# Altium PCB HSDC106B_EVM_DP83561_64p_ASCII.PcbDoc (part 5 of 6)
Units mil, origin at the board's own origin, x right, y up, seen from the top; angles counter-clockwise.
Board outline 8750.24 x 6394.7 mil, 6 copper layers (Top Layer, GND, SIG1, SIG2, GND1, Bottom Layer), stack 60.4 mil thick; 475 components, 330 nets, 1628 pads, 1086 vias.
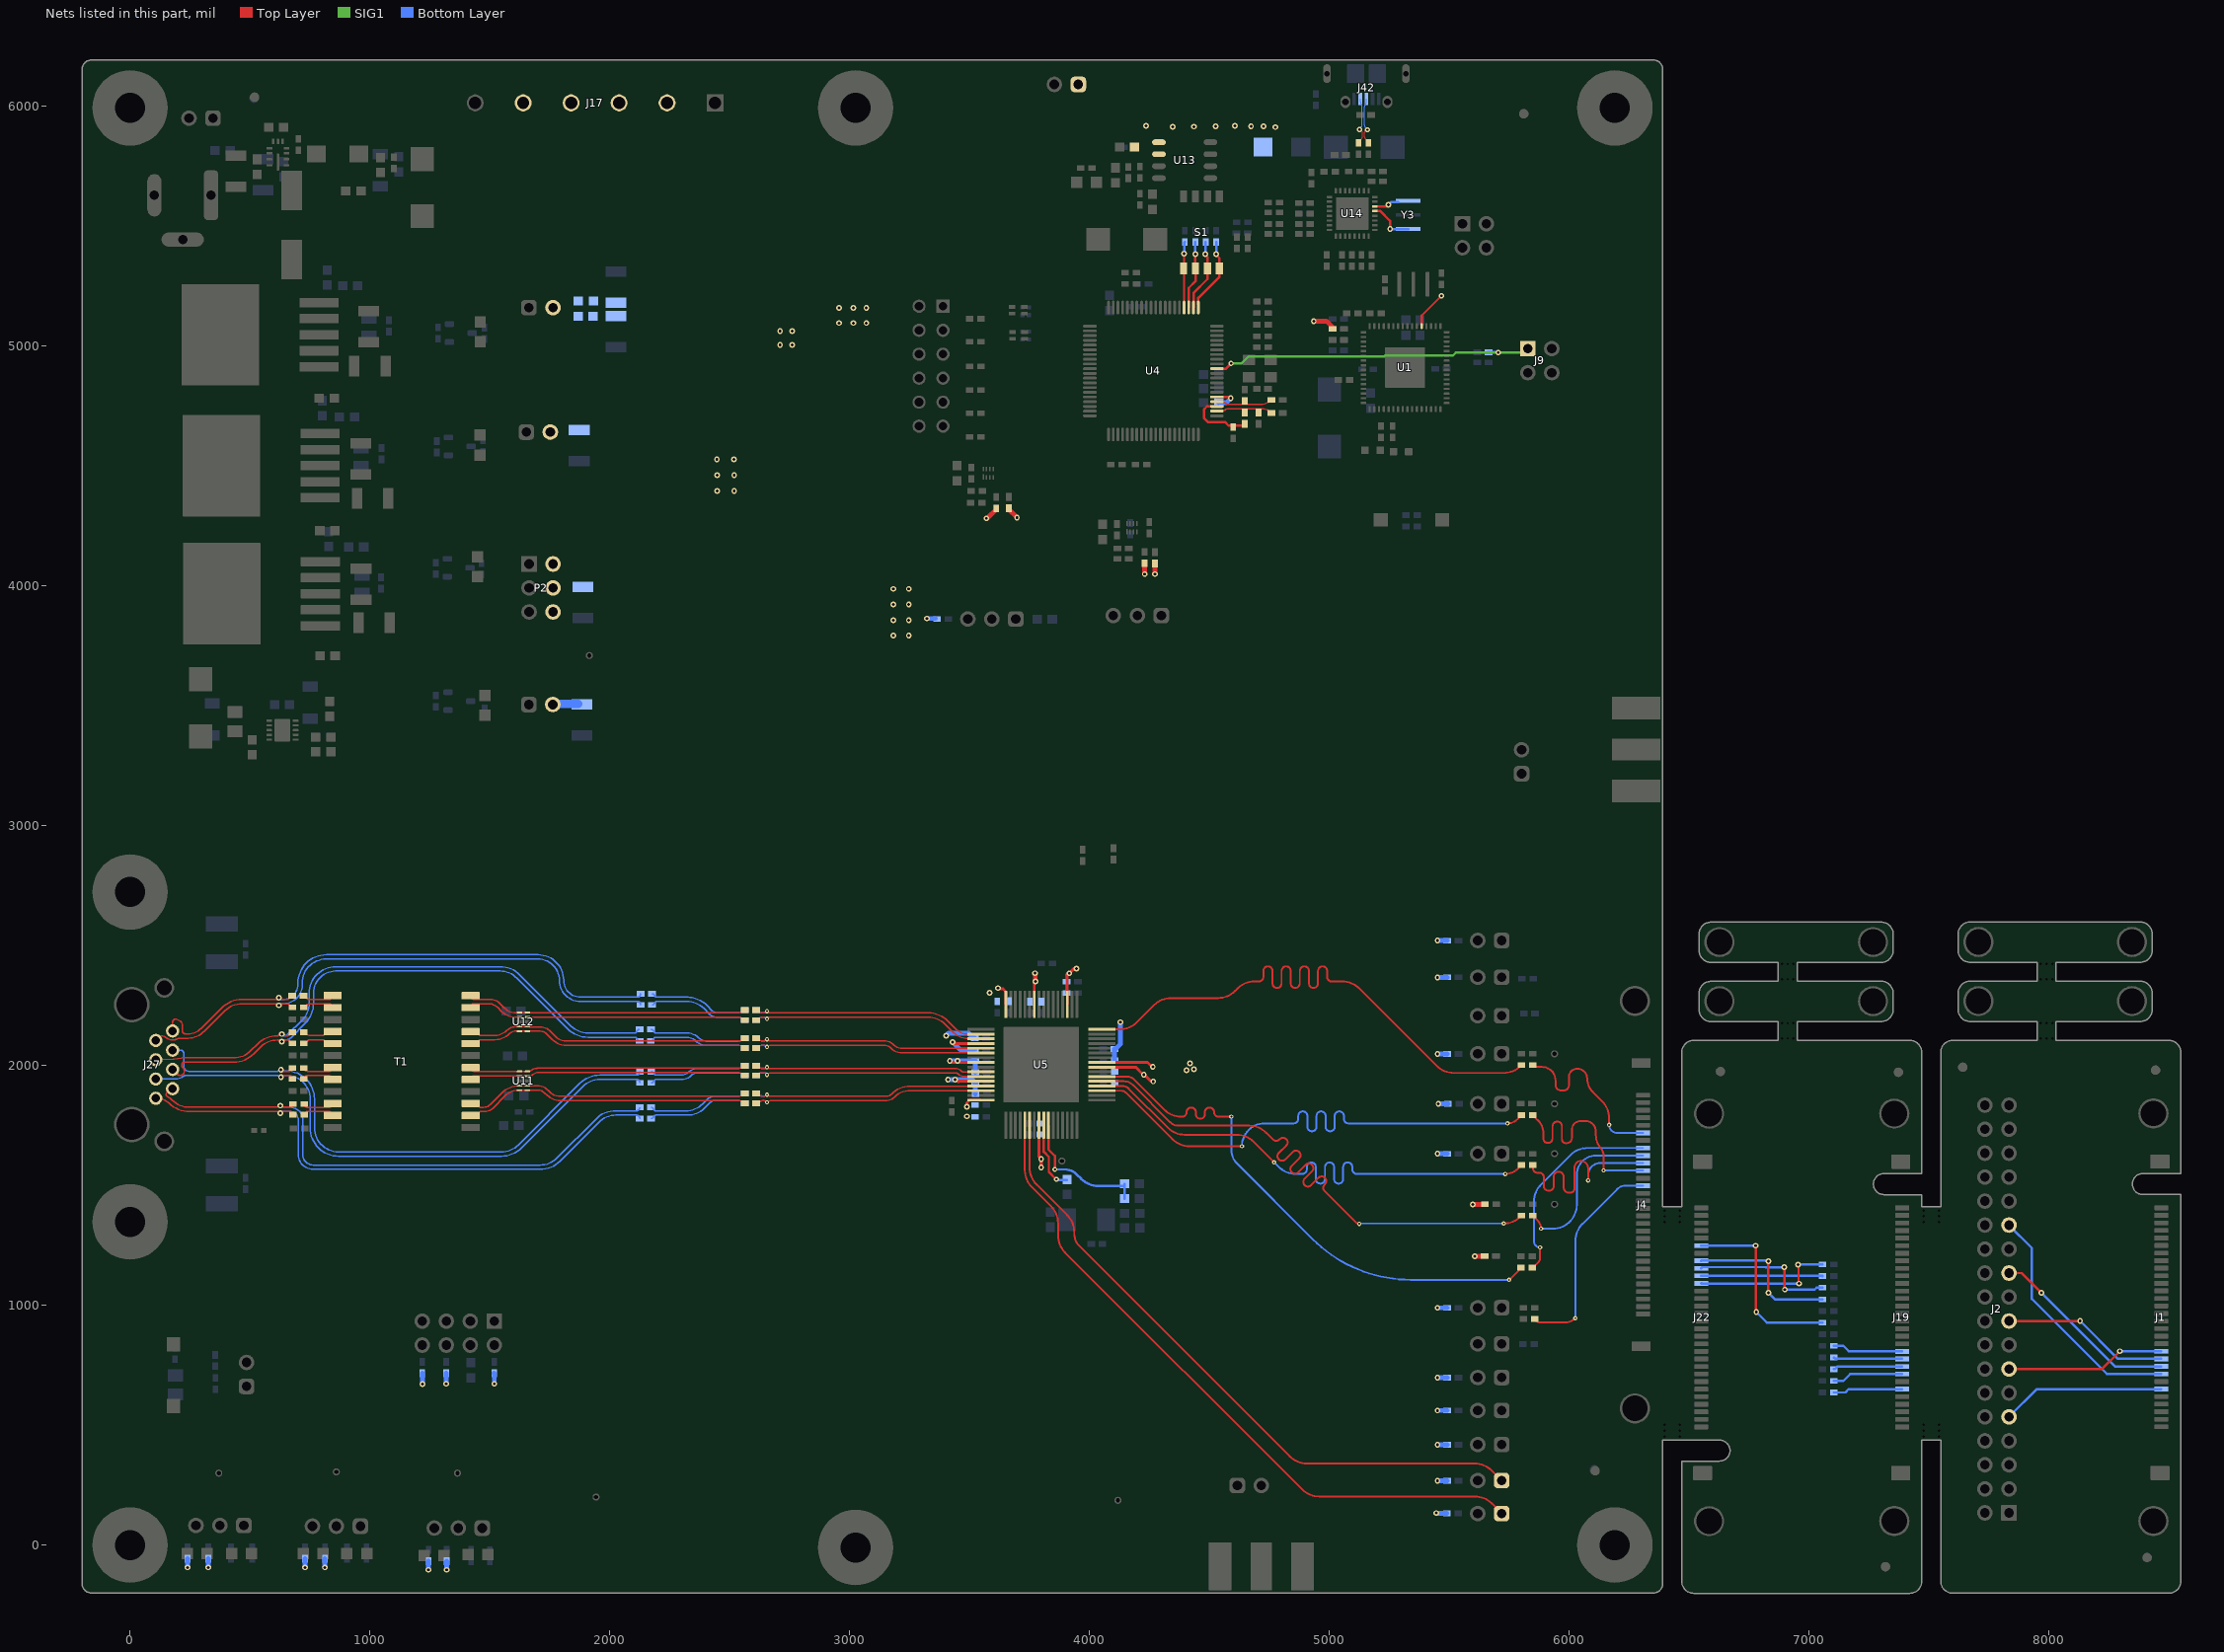
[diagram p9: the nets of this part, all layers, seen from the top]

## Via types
v1: diameter 24, hole 12, Top Layer to Bottom Layer, tented both sides, 905 vias
v2: diameter 24, hole 12, Top Layer to Bottom Layer, 63 vias
v3: diameter 18, hole 7.87, Top Layer to Bottom Layer, tented both sides, 53 vias
v4: diameter 22, hole 10, Top Layer to Bottom Layer, tented both sides, 43 vias
v5: diameter 19.68, hole 7.87, Top Layer to Bottom Layer, 21 vias
v6: diameter 22, hole 12, Top Layer to Bottom Layer, tented both sides, 1 vias

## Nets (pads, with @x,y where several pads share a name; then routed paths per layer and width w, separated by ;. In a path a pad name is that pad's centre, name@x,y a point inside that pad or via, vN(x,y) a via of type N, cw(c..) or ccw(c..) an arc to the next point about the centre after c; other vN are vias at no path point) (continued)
SW1: R65.1 S1.4 U4.1 | length 305.1
  Top Layer w10: U4.1@4453.48,5172.05 4453.48,5201.49 4542,5290.01 S1.4@4542,5324.7 4542,5366.42 4528.6,5379.82 v1(4528.6,5383.61)
  Bottom Layer w10: v1(4528.6,5383.61) R65.1@4528.6,5434.98
SW2: R64.1 S1.3 U4.2 | length 302
  Top Layer w10: U4.2@4433.8,5161.23 4433.8,5221.8 4492,5280.01 S1.3@4492,5324.7 4492,5371.16 4483.34,5379.82 v1(4483.34,5383.61)
  Bottom Layer w10: v1(4483.34,5383.61) 4483.97,5384.24 4483.97,5434.35 R64.1@4484.6,5434.98
SW3: R63.1 S1.2 U4.3 | length 285.5
  Top Layer w10: U4.3@4414.11,5161.23 4414.11,5243.12 4442,5271.01 S1.2@4442,5324.7 4441.6,5325.1 v1(4441.6,5383.61)
  Bottom Layer w10: v1(4441.6,5383.61) R63.1@4441.6,5434.98
SW4: R62.1 S1.1 U4.4 | length 277.1
  Top Layer w10: U4.4@4394.43,5161.23 4394.43,5322.27 S1.1@4392,5324.7 4394.6,5327.3 v1(4394.6,5385.61)
  Bottom Layer w10: v1(4394.6,5385.61) 4396.1,5387.11 4396.1,5433.48 R62.1@4397.6,5434.98
TARGET_D_N: C123.1 R180.1 U4.64 | length 240.4
  Top Layer w6: U4.64@4531.24,4768.51 4547.67,4768.51 cw(c4547.67,4732.03) 4573.46,4757.83 4713.55,4757.83 ccw(c4713.55,4823.21) C123.1@4759.78,4776.98 ; C123.1@4759.78,4775.98 C123.1@4762.5,4778.7
TARGET_D_P: C122.1 R73.2 R183.1 U4.62 | length 240.6
  Top Layer w6: U4.62@4531.24,4729.14 4547.67,4729.14 ccw(c4547.67,4765.62) 4573.46,4739.83 4718.6,4739.83 cw(c4718.6,4692.07) 4752.36,4725.84 C122.1@4761.5,4716.7
TARGET_PUR: R73.1 R74.1 U4.63 | length 287.8
  Top Layer w10: U4.63@4535.36,4749.4 4490.25,4749.4 4477.12,4736.27 4477.12,4700.27 4493.74,4683.65 4564.74,4683.65 4579.74,4668.65 4599.6,4668.65 R73.1@4652.12,4668.65
TD_A_cap_N: C97.1 R124.1 | length 416.9
  Bottom Layer w6: C97.1@2176.22,2252.61 ccw(c2176.22,2262.11) 2182.94,2255.39 2188.2,2260.65 ccw(c2186.34,2262.5) 2188.97,2262.5 cw(c2191.59,2262.5) 2189.74,2264.36 cw(c2196.37,2257.73) 2193.36,2266.61 cw(c2196.37,2257.73) 2196.37,2267.11 2321.73,2267.11 cw(c2321.73,2167.11) 2331.67,2266.61 cw(c2321.73,2167.11) 2392.44,2237.82 2413.77,2216.48 ; 2413.78,2216.48 ccw(c2449.46,2252.17) 2449.46,2201.7 2534.06,2201.7 cw(c2534.06,2160.73) R124.1@2563.03,2189.7
TD_A_cap_P: C95.1 R120.1 | length 416.9
  Bottom Layer w6: C95.1@2176.22,2299.61 cw(c2176.22,2290.1) 2182.94,2296.82 2188.2,2291.56 cw(c2186.34,2289.71) 2188.97,2289.71 ccw(c2191.59,2289.71) 2189.74,2287.85 ccw(c2196.37,2294.48) 2196.37,2285.11 2321.76,2285.11 cw(c2321.76,2167.19) 2332.56,2284.61 cw(c2321.76,2167.19) 2405.14,2250.57 2426.5,2229.21 ccw(c2449.46,2252.17) 2449.46,2219.7 2534.06,2219.7 ccw(c2534.06,2260.67) R120.1@2563.03,2231.7
TD_A_mag_N: R125.2 T1.14 | length 149.8
  Top Layer w6: R125.2@723.62,2243 ccw(c723.62,2252.51) 730.34,2245.78 737.49,2252.93 cw(c749,2241.43) 749,2257.7 828.66,2257.7 cw(c828.66,2241.7) T1.14@844.66,2241.7 T1.14@830.58,2241.7 ; T1.14@810.16,2253.66 T1.14@810.16,2254.18
TD_A_mag_P: R128.2 T1.13 | length 135.6
  Top Layer w6: R128.2@723.22,2290.61 cw(c723.22,2281.1) 729.94,2287.82 737.16,2280.6 ccw(c749,2292.45) 749,2275.7 828.66,2275.7 ccw(c828.66,2291.7) T1.13@844.66,2291.7
TD_A_N: R122.2 R124.2 U5.3 | length 1025.2
  Top Layer w6: R122.2@2612.07,2189.71 cw(c2640.17,2161.58) 2640.17,2201.35 2641.88,2201.35 cw(c2641.88,2179.08) v3@2656.8,2195.61 ; U5.3@3547.71,2111.49 ccw(c3545.67,2109.46) 3545.67,2112.34 3494.75,2112.34 cw(c3494.75,2200.56) 3432.37,2138.18 3398.13,2172.41 ccw(c3327.42,2101.7) 3327.42,2201.7 2672.74,2201.7 ccw(c2672.74,2177.8) v3@2656.8,2195.61 ; v3(2655.84,2194.7) cw(c2672.59,2177.95) v3@2656.8,2195.6 ; v3(2655.84,2194.7) cw(c2672.74,2177.8) v3@2656.8,2195.6 ; v3(2655.84,2194.7) 2655.89,2194.7 v3@2656.8,2195.6
  Bottom Layer w6: R124.2@2610.28,2189.7 cw(c2638.39,2161.58) 2638.39,2201.35 2640.1,2201.35 cw(c2640.1,2179.08) v3@2655.84,2194.83
TD_A_P: R119.2 R120.2 U5.2 | length 1058.8
  Top Layer w6: R119.2@2612.07,2231.69 ccw(c2640.17,2259.82) 2640.17,2220.05 2641.88,2220.05 ccw(c2641.88,2242.32) v3@2656.73,2225.73 ; v3(2655.84,2226.57) ccw(c2672.59,2243.32) v3@2656.73,2225.73 ; U5.2@3511.4,2131.18 U5.2@3547.71,2131.18 cw(c3545.67,2133.21) 3545.67,2130.34 3494.88,2130.34 cw(c3494.88,2200.88) 3445,2151 3410.79,2185.21 ccw(c3327.52,2101.94) 3327.52,2219.7 2671.29,2219.7 cw(c2671.29,2240.29) v3@2656.73,2225.73
  Bottom Layer w6: R120.2@2610.28,2231.7 ccw(c2638.39,2259.82) 2638.39,2220.05 2640.1,2220.05 ccw(c2640.1,2242.32) v3(2655.84,2226.57)
TD_A_RJ_N: C97.2 J27.7 R125.1 | length 2363.1
  Top Layer w6: J27.7@115.63,2110.19 124.51,2119.07 cw(c134,2109.58) 134,2123 cw(c134,2106.1) 141.89,2121.05 142.96,2120.43 158.54,2111.46 ccw(c177.52,2144.42) 169.48,2107.25 ccw(c177.52,2144.42) 187.85,2107.82 ccw(c177.52,2144.42) 191.95,2109.23 ccw(c177.52,2144.42) 194.5,2110.38 199.16,2112.7 cw(c201.84,2107.34) 201.84,2113.34 234.62,2113.34 234.96,2113.34 ccw(c234.24,2249.72) 250.9,2114.36 ccw(c238.48,2215.27) 310.38,2143.38 395.43,2228.43 cw(c466.14,2157.72) 466.14,2257.72 613.69,2257.72 cw(c613.69,2250.87) v1(620.54,2250.87) ; v1@620.54,2257.72 635.86,2257.72 cw(c637.26,2245.96) 637.26,2257.8 647.2,2257.8 647.29,2257.72 656.34,2257.72 cw(c656.34,2248.61) 662.78,2255.05 cw(c660.74,2253.01) 663.63,2253.01 ccw(c666.52,2253.01) 664.47,2250.97 669.66,2245.78 ccw(c676.38,2252.51) R125.1@676.38,2243
  Bottom Layer w6: v1(620.54,2250.87) cw(c627.48,2250.87) 627.48,2257.8 639.26,2257.8 ccw(c639.26,2336.54) 718,2336.54 718,2344 cw(c818,2344) 818,2444 1701,2444 cw(c1701,2355) 1790,2355 ccw(c1877.89,2355) 1803,2309 ccw(c1877.89,2355) 1877.89,2267.11 2114.48,2267.11 cw(c2114.48,2252.61) C97.2@2128.98,2252.61
TD_A_RJ_P: C95.2 J27.8 R128.1 | length 2378.9
  Top Layer w6: J27.8@177.52,2144.42 177.52,2181.22 cw(c189.43,2181.22) 189.43,2193.14 cw(c189.43,2164.04) 218.53,2164.04 218.53,2143.47 ccw(c229.76,2143.47) 229.76,2132.24 248.81,2132.24 ccw(c238.48,2215.27) 275.5,2140.23 ccw(c238.39,2215.5) 297.69,2156.14 382.74,2241.19 cw(c466.09,2157.83) 466.09,2275.72 613.52,2275.72 ccw(c613.52,2282.74) v1(620.54,2282.74) cw(c620.54,2270.98) v1@628.86,2279.3 ; v1@628.88,2279.27 ccw(c637.26,2287.65) 637.26,2275.8 654.66,2275.8 654.74,2275.72 657.23,2275.72 ccw(c657.23,2281.72) 661.47,2277.48 662.32,2278.33 ccw(c660.14,2280.52) 663.23,2280.52 cw(c666.32,2280.52) 664.13,2282.7 669.26,2287.82 cw(c675.98,2281.1) R128.1@675.98,2290.61
  Bottom Layer w6: v1(620.54,2282.74) ccw(c627.48,2282.74) 627.48,2275.8 635.65,2275.8 ccw(c635.65,2340.15) 700,2340.15 700,2344 cw(c818,2344) 818,2462 1701,2462 cw(c1701,2355) 1808,2355 ccw(c1877.89,2355) 1817.31,2320.14 ccw(c1877.89,2355) 1877.89,2285.11 2114.48,2285.11 ccw(c2114.48,2299.61) C95.2@2128.98,2299.61
TD_A_x_N: R122.1 T1.11 U12.2 U12.9 | length 1173.3
  Top Layer w6: T1.11@1419.86,2241.7 cw(c1436.16,2241.7) 1436.16,2258 1495.06,2258 cw(c1495.06,2205.03) 1532.51,2242.49 1549.96,2225.04 ccw(c1606.3,2281.38) 1606.3,2201.7 2534.06,2201.7 cw(c2534.06,2160.73) R122.1@2563.03,2189.7
TD_A_x_P: R119.1 T1.12 U12.1 U12.10 | length 1173.4
  Top Layer w6: T1.12@1419.86,2291.7 ccw(c1435.56,2291.7) 1435.56,2276 1502.52,2276 cw(c1502.52,2223.03) 1539.96,2260.49 1560.44,2240.02 ccw(c1609.49,2289.06) 1609.49,2219.7 2534.06,2219.7 ccw(c2534.06,2260.67) R119.1@2563.03,2231.7
TD_B_cap_N: C101.1 R133.1 | length 413
  Bottom Layer w6: C101.1@2171.64,2102.61 ccw(c2171.64,2112.11) 2178.36,2105.39 2183.39,2110.42 ccw(c2180.97,2112.83) 2184.39,2112.83 cw(c2187.8,2112.83) 2185.39,2115.24 cw(c2191.46,2109.17) 2187.17,2116.61 cw(c2191.46,2109.17) 2191.46,2117.76 2322.17,2117.76 cw(c2322.17,2066.02) 2358.76,2102.61 2358.81,2102.56 ccw(c2404.33,2148.08) 2404.33,2083.7 2533.28,2083.7 ; 2534.03,2083.7 cw(c2534.03,2042.73) R133.1@2561.96,2072.7 ; R133.1@2559.84,2072.7 R133.1@2561.96,2072.7 ; R133.1@2563,2071.7 ccw(c2534.03,2042.73) R133.1@2561.96,2072.7 ; R133.1@2563.03,2072.7 R133.1@2561.96,2072.7
TD_B_cap_P: C99.1 R129.1 | length 412.9
  Bottom Layer w6: C99.1@2171.81,2150.98 cw(c2171.81,2141.48) 2178.53,2148.2 2183.53,2143.2 cw(c2181.06,2140.72) 2184.56,2140.72 ccw(c2188.06,2140.72) 2185.58,2138.25 ccw(c2191.59,2144.26) 2191.59,2135.76 2322.25,2135.76 cw(c2322.25,2066.21) 2371.43,2115.39 2371.49,2115.33 ccw(c2404.4,2148.25) 2404.4,2101.7 2533.28,2101.7 ; 2534.03,2101.7 ccw(c2534.03,2142.67) R129.1@2561.96,2112.7 ; R129.1@2559.84,2112.7 R129.1@2561.96,2112.7 ; R129.1@2563,2113.7 cw(c2534.03,2142.67) R129.1@2561.96,2112.7 ; R129.1@2563.03,2112.7 R129.1@2561.96,2112.7
TD_B_mag_N: R118.2 T1.17 | length 123.6
  Top Layer w6: R118.2@731.34,2094.78 R118.2@740.18,2103.62 ; R118.2@740.19,2103.63 cw(c750.02,2093.78) 750.02,2107.7 801.68,2107.7 cw(c801.68,2095.7) 810.16,2104.19 810.16,2103.66 816.14,2097.68 ccw(c830.58,2112.12) 830.58,2091.7 T1.17@844.66,2091.7
TD_B_mag_P: R121.2 T1.16 | length 153.8
  Top Layer w6: R121.2@724.43,2138.61 R121.2@728.37,2134.67 ; T1.16@844.66,2141.7 830.58,2141.7 ccw(c830.58,2121.28) 816.14,2135.72 810.16,2129.74 810.16,2129.21 cw(c801.68,2137.7) 801.68,2125.7 750.02,2125.7 ; R121.2@728.37,2134.67 ccw(c750.02,2156.32) 750.02,2125.7 ; R121.2@728.37,2134.67 ccw(c750.02,2156.32) 728.43,2134.61 ccw(c750.02,2156.32) 750.02,2125.7
TD_B_N: R131.2 R133.2 U5.6 | length 1004
  Top Layer w6: R131.2@2610.28,2072.7 2612.19,2072.7 cw(c2640.29,2044.57) 2640.29,2084.33 2642,2084.33 cw(c2642,2062.07) v3@2656.94,2078.57 ; v3(2655.83,2077.52) cw(c2672.92,2060.43) v3@2656.94,2078.57 ; U5.6@3547.71,2052.44 ccw(c3545.67,2050.41) 3545.67,2053.28 3218.39,2053.28 cw(c3218.39,2117.09) 3173.27,2071.97 ccw(c3142.77,2041.47) 3142.77,2084.61 2672.92,2084.61 ccw(c2672.92,2060.43) v3@2656.94,2078.57
  Bottom Layer w6: R133.2@2610.28,2072.54 cw(c2638.38,2044.41) 2638.38,2084.17 2640.09,2084.17 cw(c2640.09,2061.91) v3@2655.83,2077.65
TD_B_P: R127.2 R129.2 U5.5 | length 1001.7
  Top Layer w6: R127.2@2612.19,2114.67 ccw(c2640.29,2142.81) 2640.29,2103.04 2642,2103.04 ccw(c2642,2125.3) v3@2656.69,2108.58 ; v3(2655.83,2109.4) ccw(c2672.23,2125.8) v3@2656.69,2108.58 ; U5.5@3547.71,2072.12 cw(c3545.67,2074.16) 3545.67,2071.28 3218.39,2071.28 cw(c3218.39,2117.09) 3186,2084.7 ccw(c3142.77,2041.47) 3142.77,2102.61 2672.23,2102.61 cw(c2672.23,2125.8) v3@2656.69,2108.58
  Bottom Layer w6: R129.2@2610.28,2114.51 ccw(c2638.38,2142.64) 2638.38,2102.88 2640.09,2102.88 ccw(c2640.09,2125.14) v3(2655.83,2109.4)
TD_B_RJ_N: C101.2 J27.4 R118.1 | length 2392.8
  Top Layer w6: J27.4@177.52,1983.79 200,1961.31 ccw(c208,1969.31) 208,1958 ccw(c208,1976.38) 221,1963.38 ccw(c209.63,1974.75) 225.7,1974.75 225.7,1977.07 ccw(c203.7,1977.07) 219.26,1992.63 cw(c228.66,2002.04) 215.36,2002.04 cw(c227.16,2002.04) 218.82,2010.37 ; 218.85,2010.41 cw(c227.68,2001.51) 227.68,2014.04 432.22,2014.04 ccw(c432.22,2131.91) 515.57,2048.57 544.01,2077.01 cw(c614.72,2006.3) 614.72,2106.3 616.25,2106.3 cw(c616.25,2094.38) 624.68,2102.81 ccw(c633,2111.13) v1(633,2099.37) ccw(c633,2111.13) v1@641.32,2102.81 ; v1@641.34,2102.83 cw(c649.71,2094.46) 649.71,2106.3 657.02,2106.3 cw(c657.02,2096.51) 663.94,2103.43 cw(c662.29,2101.78) 664.63,2101.78 ccw(c666.97,2101.78) 665.32,2100.13 670.66,2094.78 ccw(c677.38,2101.51) R118.1@677.38,2092
  Bottom Layer w6: v1(633,2099.37) cw(c639.94,2099.37) 639.94,2106.3 646.42,2106.3 ccw(c646.42,2139.73) 670.06,2116.09 730.47,2176.51 ccw(c647.11,2259.87) 765,2259.87 765,2302 cw(c857,2302) 857,2394 1542.58,2394 cw(c1542.58,2294) 1613.29,2364.71 1825.67,2152.33 ccw(c1909.05,2235.71) 1908.9,2117.79 ccw(c1909.05,2235.71) 1909.05,2117.79 2089.29,2117.79 2089.33,2117.83 2104.61,2117.83 cw(c2104.61,2109.33) 2110.62,2115.34 cw(c2108.15,2112.87) 2111.65,2112.87 ccw(c2115.15,2112.87) 2112.67,2110.4 C101.2@2117.67,2105.39 ; C101.2@2117.7,2105.36 ccw(c2124.39,2112.11) C101.2@2124.39,2102.61
TD_B_RJ_P: C99.2 J27.5 R121.1 | length 2396.8
  Top Layer w6: J27.5@107.44,2023.95 178.66,2026.09 ccw(c177.52,2064.11) 183.49,2026.54 198.38,2028.9 198.92,2028.98 214.06,2031.38 cw(c222.49,1978.51) 222.49,2032.04 432.17,2032.04 ccw(c432.17,2132.04) 502.88,2061.33 532.83,2091.28 cw(c612.55,2011.56) 612.55,2124.3 616.25,2124.3 ccw(c616.25,2136.23) 624.68,2127.8 cw(c633,2119.48) v1(633,2131.24) cw(c633,2119.48) v1@641.32,2127.8 ; v1@641.34,2127.77 ccw(c649.71,2136.15) 649.71,2124.3 656.94,2124.3 ccw(c656.94,2133.92) 663.74,2127.12 ccw(c662.05,2128.81) 664.44,2128.81 cw(c666.83,2128.81) 665.14,2130.49 670.47,2135.82 cw(c677.19,2129.1) R121.1@677.19,2138.61
  Bottom Layer w6: v1(633,2131.24) ccw(c639.94,2131.24) 639.94,2124.3 646.37,2124.3 ccw(c646.37,2139.84) 657.36,2128.85 717.71,2189.2 ccw(c647,2259.91) 747,2259.91 747,2302 cw(c857,2302) 857,2412 1542.61,2412 cw(c1542.61,2294.08) 1625.99,2377.46 1838.37,2165.08 ccw(c1909.08,2235.79) 1909.08,2135.79 2081.84,2135.79 2081.87,2135.83 2104.75,2135.83 ccw(c2104.75,2144.42) 2110.81,2138.33 ; 2110.84,2138.37 ccw(c2108.41,2140.76) C99.2@2111.82,2140.73 ; C99.2@2111.82,2140.79 cw(c2115.23,2140.76) 2112.8,2143.15 2117.85,2148.2 cw(c2124.57,2141.48) C99.2@2124.57,2150.98
TD_B_x_N: R131.1 T1.8 U12.5 U12.6 | length 1179.7
  Top Layer w6: T1.8@1419.86,2091.7 1433.94,2091.7 ccw(c1433.94,2112.12) 1448.38,2097.68 1454.36,2103.66 1454.36,2104.19 cw(c1462.84,2095.7) 1462.84,2107.7 1521.42,2107.7 ccw(c1521.42,2195.32) 1583.33,2133.32 ccw(c1521.42,2195.32) 1583.38,2133.36 cw(c1608.54,2108.2) 1608.54,2143.79 1623.28,2143.79 U12.5@1624.13,2142.94 cw(c1626.16,2140.91) 1626.16,2143.79 1657.61,2143.79 cw(c1657.61,2142.44) 1658.56,2143.39 ccw(c1659.51,2144.34) 1659.51,2143 1711,2143 cw(c1711,2107.26) 1736.27,2132.53 1761.1,2107.7 ccw(c1816.86,2163.46) 1816.86,2084.61 2532.38,2084.61 cw(c2532.38,2043.96) R131.1@2561.12,2072.7
TD_B_x_P: R127.1 T1.9 U12.4 U12.7 | length 1181.4
  Top Layer w6: T1.9@1419.86,2141.7 1433.94,2141.7 cw(c1433.94,2121.28) 1448.38,2135.72 1454.36,2129.74 1454.36,2129.21 ccw(c1462.84,2137.7) 1462.84,2125.7 1521.32,2125.7 ccw(c1521.32,2195.56) 1570.69,2146.13 cw(c1608.44,2108.44) 1570.78,2146.22 cw(c1608.44,2108.44) 1608.44,2161.79 1623.28,2161.79 U12.4@1624.13,2162.63 ccw(c1626.16,2164.66) 1626.16,2161.79 1665.07,2161.79 cw(c1665.07,2160.44) 1666.02,2161.39 ccw(c1666.97,2162.34) 1666.97,2161 1711.08,2161 cw(c1711.08,2107.47) 1748.94,2145.32 1773.73,2120.53 ccw(c1817,2163.8) 1816.89,2102.61 ccw(c1817,2163.8) 1817,2102.61 2532.38,2102.61 ccw(c2532.38,2143.25) 2535.49,2102.72 ccw(c2532.38,2143.25) 2561.12,2114.51 R127.1@2562.84,2114.51
TD_C_cap_N: C104.1 R140.1 | length 409
  Bottom Layer w6: C104.1@2173.22,1927.61 ccw(c2173.22,1937.11) 2179.94,1930.39 2185.2,1935.65 ccw(c2183.34,1937.5) 2185.97,1937.5 cw(c2188.59,1937.5) 2186.74,1939.36 cw(c2193.37,1932.73) 2190.36,1941.61 cw(c2193.37,1932.73) 2193.37,1942.11 2300.77,1942.11 ccw(c2300.77,1996.16) 2339,1957.94 ; 2339.03,1957.97 cw(c2366.89,1930.11) 2366.89,1969.51 2533.28,1969.51 ; 2534.03,1969.7 cw(c2534.03,1928.73) R140.1@2562.17,1958.51 ; R140.1@2559.84,1958.51 R140.1@2562.17,1958.51 ; R140.1@2563,1957.7 ccw(c2534.03,1928.73) R140.1@2562.17,1958.51 ; R140.1@2563.03,1958.51 R140.1@2562.17,1958.51
TD_C_cap_P: C103.1 R138.1 | length 409
  Bottom Layer w6: C103.1@2173.22,1974.61 cw(c2173.22,1965.1) 2179.94,1971.82 2185.2,1966.56 cw(c2183.34,1964.71) 2185.97,1964.71 ccw(c2188.59,1964.71) 2186.74,1962.85 ccw(c2193.37,1969.48) 2193.37,1960.11 2300.73,1960.11 ccw(c2300.73,1996.28) 2326.3,1970.7 ; 2326.33,1970.73 cw(c2366.84,1930.23) 2366.84,1987.51 2533.28,1987.51 ; 2534.03,1987.7 ccw(c2534.03,2028.67) R138.1@2561.76,1998.51 ; R138.1@2559.84,1998.51 R138.1@2561.76,1998.51 ; R138.1@2563,1999.7 cw(c2534.03,2028.67) R138.1@2561.76,1998.51 ; R138.1@2563.03,1998.51 R138.1@2561.76,1998.51
TD_C_mag_N: R115.2 T1.20 | length 137.2
  Top Layer w6: R115.2@725,1943 cw(c739.7,1943) 739.7,1957.7 828.66,1957.7 cw(c828.66,1941.7) T1.20@844.66,1941.7
TD_C_mag_P: R116.2 T1.19 | length 137.5
  Top Layer w6: R116.2@725,1991 ccw(c740.3,1991) 740.3,1975.7 828.66,1975.7 ccw(c828.66,1991.7) T1.19@844.66,1991.7
TD_C_N: R139.2 R140.2 U5.11 | length 1001.8
  Top Layer w6: R139.2@2610.28,1958.51 cw(c2638.38,1930.38) 2638.38,1970.14 2640.09,1970.14 cw(c2640.09,1947.88) v3@2655.83,1963.62 ; v3(2655.83,1961.52) cw(c2675.11,1942.24) 2675.11,1969.51 3442.18,1969.51 cw(c3442.18,1954.47) 3452.81,1965.11 ; 3452.84,1965.08 ccw(c3477.51,1989.74) 3477.51,1954.86 3545.67,1954.86 cw(c3545.67,1951.98) U5.11@3547.71,1954.01
  Bottom Layer w6: R140.2@2610.28,1958.51 ccw(c2610.28,1968.02) 2617,1961.29 2618.54,1962.84 cw(c2634.65,1946.72) 2634.65,1969.51 2647.84,1969.51 cw(c2647.84,1961.52) v3(2655.83,1961.52)
TD_C_P: R137.2 R138.2 U5.10 | length 999.3
  Top Layer w6: R137.2@2610.28,1998.51 2612.4,1998.51 ccw(c2638.38,2028.62) 2638.38,1988.85 2640.09,1988.85 ccw(c2640.09,2011.12) v3@2655.83,1995.37 ; v3(2655.83,1993.4) ccw(c2670.04,2007.61) 2670.04,1987.51 3442.24,1987.51 cw(c3442.24,1954.63) 3465.49,1977.88 3465.54,1977.83 ccw(c3477.55,1989.85) 3477.55,1972.86 3545.67,1972.86 ccw(c3545.67,1975.73) U5.10@3547.71,1973.7
  Bottom Layer w6: R138.2@2610.28,1998.51 cw(c2610.28,1989.01) 2617,1995.73 2618.54,1994.19 ccw(c2634.65,2010.3) 2634.65,1987.51 2649.94,1987.51 ccw(c2649.94,1993.4) v3(2655.83,1993.4)
TD_C_RJ_N: C104.2 J27.3 R115.1 | length 2464.5
  Top Layer w6: v1(629.38,1951.06) cw(c636.31,1951.06) 636.31,1958 663.38,1958 cw(c663.38,1944) R115.1@677.38,1944
  Bottom Layer w6: J27.3@107.44,1943.64 190.32,1943.64 ccw(c190.32,1992.68) 222.14,1955.36 ; 217.62,1951.94 cw(c232.26,1937.3) 222.14,1955.36 ; v1(629.38,1951.06) cw(c629.38,1962.82) 621.06,1954.51 ccw(c612.63,1946.07) 612.63,1958 232.26,1958 ccw(c232.26,1937.3) 222.14,1955.36 ; v1@629.38,1959 651.79,1959 cw(c651.79,1859.79) 751,1859.79 751,1740 ccw(c869,1740) 869,1622 1548.64,1622 ccw(c1548.64,1739.86) 1631.98,1656.52 1888.27,1912.82 cw(c1958.98,1842.11) 1958.98,1942.11 2111.48,1942.11 cw(c2111.48,1927.61) C104.2@2125.98,1927.61
TD_C_RJ_P: C103.2 J27.6 R116.1 | length 2459.1
  Top Layer w6: v1(629.38,1982.94) ccw(c636.31,1982.94) 636.31,1976 663.38,1976 ccw(c663.38,1990) R116.1@677.38,1990
  Bottom Layer w6: J27.6@177.52,2064.11 211.04,2064.11 cw(c211.04,2051.48) 223.67,2051.48 223.67,1997.33 ccw(c245,1997.33) 245,1976 612.63,1976 ccw(c612.63,1987.93) 621.06,1979.49 cw(c629.38,1971.18) v1(629.38,1982.94) ; v1@629.38,1977 651.79,1977 cw(c651.79,1859.79) 769,1859.79 769,1740 ccw(c869,1740) 869,1640 1548.58,1640 ccw(c1548.58,1740) 1619.29,1669.29 1875.58,1925.58 cw(c1958.94,1842.22) 1958.94,1960.11 2111.48,1960.11 ccw(c2111.48,1974.61) C103.2@2125.98,1974.61
TD_C_x_N: R139.1 T1.5 U11.2 U11.9 | length 1150.2
  Top Layer w6: T1.5@1419.86,1941.7 cw(c1435,1941.7) 1435,1956.84 1622.09,1956.84 cw(c1622.09,1953.97) U11.2@1624.13,1956 1624.97,1956.84 1656.16,1956.84 U11.9@1657,1956 ; U11.9@1666.49,1956.84 ccw(c1666.49,1974.84) 1679.19,1962.09 cw(c1699.98,1941.31) 1699.98,1970.7 2533.6,1970.7 cw(c2533.6,1929.08) R139.1@2563.03,1958.51
TD_C_x_P: R137.1 T1.6 U11.1 U11.10 | length 1159.3
  Top Layer w6: T1.6@1419.86,1991.7 ccw(c1436.72,1991.7) 1436.72,1974.84 1622.09,1974.84 ccw(c1622.09,1977.72) U11.1@1624.13,1975.68 ccw(c1624.97,1975.68) 1624.97,1974.84 U11.10@1654,1974.84 ; U11.10@1654.01,1975.68 U11.10@1657,1975.68 1666.18,1975.68 1667.23,1976.1 ccw(c1665.04,1981.69) 1668.28,1976.63 ccw(c1665.04,1981.69) 1669,1977.17 cw(c1699.98,1941.31) 1695.32,1988.47 1697.6,1988.7 2539.35,1988.7 ccw(c2539.35,2022.2) R137.1@2563.03,1998.51
TD_D_cap_N: C107.1 R144.1 | length 422.6
  Bottom Layer w6: C107.1@2172.22,1778.61 ccw(c2172.22,1788.11) 2178.94,1781.39 2184.2,1786.65 ccw(c2182.34,1788.5) 2184.97,1788.5 cw(c2187.59,1788.5) 2185.74,1790.36 cw(c2192.37,1783.73) 2187.29,1791.61 cw(c2192.37,1783.73) 2192.37,1793.11 2325.98,1793.11 ccw(c2325.98,1888.8) 2393.65,1821.13 2417.86,1845.35 cw(c2439.53,1823.68) 2439.53,1854.32 2533.32,1854.32 ; 2534.06,1854.51 cw(c2534.06,1813.54) R144.1@2562.2,1843.32 ; R144.1@2559.87,1843.32 R144.1@2562.2,1843.32 ; R144.1@2563.03,1842.51 ccw(c2534.06,1813.54) R144.1@2562.2,1843.32 ; R144.1@2563.06,1843.32 R144.1@2562.2,1843.32
TD_D_cap_P: C106.1 R142.1 | length 421.9
  Bottom Layer w6: C106.1@2172.22,1825.61 cw(c2172.22,1816.1) 2178.94,1822.82 2184.2,1817.56 cw(c2182.34,1815.71) 2184.97,1815.71 ccw(c2187.59,1815.71) 2185.74,1813.85 ccw(c2192.37,1820.48) 2192.37,1811.11 2318.53,1811.11 ccw(c2318.53,1906.8) 2386.19,1839.13 2405.13,1858.08 cw(c2439.53,1823.68) 2439.53,1872.32 2533.32,1872.32 ; 2534.06,1872.51 ccw(c2534.06,1913.48) R142.1@2561.79,1883.32 ; R142.1@2559.87,1883.32 R142.1@2561.79,1883.32 ; R142.1@2563.06,1883.32 R142.1@2561.79,1883.32 ; R142.1@2563.03,1884.51 cw(c2534.06,1913.48) R142.1@2561.79,1883.32
TD_D_mag_N: R112.2 T1.23 | length 134.4
  Top Layer w6: R112.2@726.62,1795 cw(c739.32,1795) 739.32,1807.7 828.66,1807.7 cw(c828.66,1791.7) T1.23@844.66,1791.7
TD_D_mag_P: R113.2 T1.22 | length 134.8
  Top Layer w6: R113.2@726.62,1839 ccw(c739.92,1839) 739.92,1825.7 828.66,1825.7 ccw(c828.66,1841.7) T1.22@844.66,1841.7
TD_D_N: R143.2 R144.2 U5.14 | length 1005.9
  Top Layer w6: R143.2@2610.28,1842.51 2612.76,1842.51 cw(c2640.87,1814.38) 2640.87,1854.15 2642.57,1854.15 cw(c2642.57,1831.88) 2657.7,1848.22 ccw(c2673.9,1828.45) v3(2655.83,1846.53) cw(c2672.58,1829.78) 2672.58,1853.46 3150.71,1853.46 ccw(c3150.71,1905.07) 3187.21,1868.58 ; 3187.24,1868.61 cw(c3252.88,1802.97) 3252.88,1895.8 3545.67,1895.8 cw(c3545.67,1892.93) U5.14@3547.71,1894.96 cw(c3545.67,1892.93) U5.14@3547.71,1894.96
  Bottom Layer w6: R144.2@2610.28,1841.54 cw(c2638.38,1813.41) 2638.38,1853.17 2639.78,1853.17 cw(c2639.78,1830.48) v3@2652.43,1849.32
TD_D_P: R141.2 R142.2 U5.13 | length 1003.6
  Top Layer w6: R141.2@2612.76,1884.49 ccw(c2640.87,1912.62) 2640.87,1872.85 2642.57,1872.85 ccw(c2642.57,1895.12) v3@2656.5,1877.75 ; v3(2655.83,1878.4) ccw(c2672.58,1895.15) v3@2656.5,1877.75 ; U5.13@3547.71,1914.64 cw(c3545.67,1916.68) 3545.67,1913.8 3252.74,1913.8 ccw(c3252.74,1803.32) 3174.61,1881.44 3174.51,1881.34 cw(c3150.67,1905.19) 3150.67,1871.46 2672.58,1871.46 cw(c2672.58,1895.15) v3@2656.5,1877.75
  Bottom Layer w6: R142.2@2610.28,1883.51 ccw(c2638.38,1911.65) 2636,1871.95 2640.26,1871.95 ccw(c2640.26,1893.97) v3(2655.83,1878.4)
TD_D_RJ_N: C107.2 J27.1 R112.1 | length 2395.7
  Top Layer w6: J27.1@107.44,1863.32 112.83,1863.32 cw(c112.83,1792.36) 162.97,1842.57 ; 163.01,1842.54 ccw(c246.39,1925.92) 246.39,1808 620.06,1808 cw(c620.06,1801.06) v1(627,1801.06) cw(c633.94,1801.06) 633.94,1808 666.38,1808 cw(c666.38,1795) R112.1@679.38,1795
  Bottom Layer w6: v1(627,1801.06) cw(c633.94,1801.06) 633.94,1808 666.5,1808 cw(c666.5,1772.5) 702,1772.5 702,1629.07 ccw(c764.07,1629.07) 764.07,1567 1709.18,1567 ccw(c1709.18,1684.86) 1792.52,1601.52 1954.82,1763.82 cw(c2025.53,1693.11) 2025.53,1793.11 2110.48,1793.11 cw(c2110.48,1778.61) C107.2@2124.98,1778.61
TD_D_RJ_P: C106.2 J27.2 R113.1 | length 2408.7
  Top Layer w6: 154.24,1871.1 cw(c157.08,1876.38) 151.31,1874.74 cw(c166.48,1879.11) 150.69,1879.11 150.69,1879.45 cw(c174.72,1879.45) 174.72,1903.48 J27.2@177.52,1903.48 ccw(c177.52,1889.22) J27.2@167.44,1899.3 ; 154.28,1871.07 cw(c112.83,1792.36) 156.47,1869.88 ; 156.48,1869.88 cw(c112.83,1792.36) 166.48,1863.32 cw(c112.83,1792.36) 175.6,1855.4 ; R113.1@679.38,1839 cw(c666.38,1839) 666.38,1826 633.94,1826 cw(c633.94,1832.94) v1(627,1832.94) cw(c620.06,1832.94) 620.06,1826 246.42,1826 cw(c246.42,1926) 175.72,1855.28 ; 175.6,1855.4 cw(c112.83,1792.36) 175.72,1855.28 ; 175.6,1855.4 175.72,1855.28
  Bottom Layer w6: v1(627,1832.94) ccw(c633.94,1832.94) 633.94,1826 666.5,1826 cw(c666.5,1772.5) 720,1772.5 720,1629.07 ccw(c764.07,1629.07) 764.07,1585 1709.12,1585 ccw(c1709.12,1685) 1779.83,1614.29 1942.12,1776.58 cw(c2025.48,1693.22) 2025.48,1811.11 2110.48,1811.11 ccw(c2110.48,1825.61) C106.2@2124.98,1825.61
TD_D_x_N: R143.1 T1.2 U11.5 U11.6 | length 1196.3
  Top Layer w6: T1.2@1419.86,1791.7 1425.48,1791.7 ccw(c1425.48,1832.54) 1454.36,1803.66 1454.36,1804.19 T1.2@1456.12,1805.94 ; T1.2@1456.13,1805.95 cw(c1460.36,1801.7) 1460.36,1807.7 1477.79,1807.7 ccw(c1477.79,1855.78) 1511.78,1821.78 1563.53,1873.53 cw(c1622.09,1814.97) 1610.66,1896.99 cw(c1622.09,1814.97) 1622.09,1897.79 cw(c1622.09,1894.91) U11.5@1624.13,1896.94 U11.6@1657,1896.94 cw(c1659.03,1894.91) 1659.03,1897.79 1696.23,1897.79 cw(c1696.23,1848.23) 1731.27,1883.27 1736.96,1877.59 ccw(c1793.87,1934.51) 1744.01,1871.31 ccw(c1793.87,1934.51) 1793.75,1854.01 ccw(c1793.87,1934.51) 1793.87,1854.01 2539.51,1854.01 cw(c2539.51,1824.99) 2560.03,1845.51 R143.1@2563.03,1842.51
TD_D_x_P: R141.1 T1.3 U11.4 U11.7 | length 1195.9
  Top Layer w6: T1.3@1419.86,1841.7 1425.48,1841.7 cw(c1425.48,1800.86) 1454.36,1829.74 1454.36,1829.21 1456.12,1827.46 ccw(c1460.36,1831.7) 1460.36,1825.7 1474.06,1825.7 ccw(c1474.06,1864.78) 1501.68,1837.14 1550.85,1886.31 cw(c1622.02,1815.13) 1622.02,1915.79 1622.09,1915.79 ccw(c1622.09,1918.66) U11.4@1624.13,1916.63 U11.7@1657,1916.63 ccw(c1659.03,1918.66) 1659.03,1915.79 1696.31,1915.79 cw(c1696.31,1848.42) 1743.94,1896.06 1749.59,1890.41 ccw(c1794,1934.81) 1760.98,1881.39 ccw(c1794,1934.81) 1793.89,1872.01 ccw(c1794,1934.81) 1794,1872.01 2539.51,1872.01 ccw(c2539.51,1901.03) 2560.03,1880.51 R141.1@2563.03,1883.51
TEST/SBWTCK: J9.1 R9.2 U4.71 | length 1373.7
  Top Layer w10: U4.71@4531.24,4906.31 4568.98,4906.31 v4(4590.28,4927.61)
  SIG1 w10: v4(4590.28,4927.61) 4633.12,4927.61 4663.34,4957.83 5229.82,4957.83 5232.77,4960.77 5515.07,4960.77 5528,4973.7 v4(5704,4973.7) 5811.69,4973.7 J9.1@5827.6,4989.61
  Bottom Layer w10: R9.2@5661.62,4974.7 R9.2@5664.22,4974.7 5703,4974.7 v4(5704,4973.7)
TX_CTRL: R31.1 U5.48 | length 2510
  Top Layer w8: U5.48@4051.41,2150.87 4127.08,2150.86 ccw(c4127.08,2250.86) 4197.79,2180.15 4269.9,2252.27 cw(c4340.61,2181.55) 4340.61,2281.55 4536.13,2281.55 ccw(c4536.13,2381.55) 4606.84,2310.84 4617.41,2321.41 cw(c4688.12,2250.7) 4633.74,2334.62 cw(c4688.12,2250.7) 4688.12,2350.7 4702,2350.7 4706,2350.7 ccw(c4706,2369.7) 4725,2369.7 4725,2394.59 cw(c4744,2394.59) 4763,2394.59 4763,2342.49 ccw(c4782,2342.49) 4801,2342.49 4801,2394.59 cw(c4820,2394.59) 4839,2394.59 4839,2342.49 ccw(c4858,2342.49) 4877,2342.49 4877,2394.59 cw(c4896,2394.59) 4915,2394.59 4915,2342.49 ccw(c4934,2342.49) 4953,2342.49 4953,2394.59 cw(c4972,2394.59) 4991,2394.59 4991,2369.7 ccw(c5010,2369.7) 5010,2350.7 5048.91,2350.7 5054.58,2350.7 cw(c5054.58,2250.7) 5125.29,2321.41 5448.33,1998.37 ccw(c5519.04,2069.08) 5519.04,1969.08 5727.43,1969.08 ccw(c5727.43,2069.08) 5798.14,1998.37 R31.1@5801.34,2001.57
TX_CTRL_1: J1.50 J2.9 | length 683.6
  Bottom Layer w10: J2.9@7833.6,534.61 7949.78,650.79 J1.50@8469.11,650.79
TX_CTRL_2: J22.50 R207.1 | length 799.8
  Top Layer w10: v1(6777.6,1248.61) 6779.1,1247.11 6779.1,974.11 v1(6780.6,972.61)
  Bottom Layer w10: J22.50@6550.68,1248.82 6550.89,1248.61 v1(6777.6,1248.61) ; v1(6780.6,972.61) 6780.6,971.59 6824.31,927.88 R207.1@7056.98,927.88
TX_CTRL_CS: J4.50 R31.2 | length 767.2
  Top Layer w8: R31.2@5848.59,2001.57 ccw(c5866.63,2019.62) 5866.63,1994.1 5887.15,1994.1 cw(c5887.15,1938.13) 5943.11,1938.13 5943.11,1918.89 ccw(c5965.51,1918.89) 5965.51,1896.49 5977.8,1896.49 ccw(c5977.8,1917.44) 5998.75,1917.44 5998.75,1951.75 cw(c6034,1951.75) 6034,1987 cw(c6034,1946) 6075,1946 ccw(c6152.25,1946) 6097.63,1891.37 6137.31,1851.69 cw(c6066.6,1780.98) 6166.6,1780.98 v3(6166.6,1752.72)
  Bottom Layer w8: v3(6166.6,1752.72) ccw(c6200.11,1752.72) 6200.11,1719.21 J4.50@6308.86,1719.21
TX_CTRL_LP: J19.50 R130.2 | length 290.2
  Bottom Layer w10: R130.2@7104.22,636.61 7151.41,636.61 7165.5,650.7 J19.50@7388.6,650.7
TX_D0: R29.1 U5.38 | length 2292.9
  Top Layer w8: U5.38@4051.41,1954.01 4159.01,1954.01 cw(c4159.01,1918.58) 4184.05,1943.65 4311.7,1816 ccw(c4382.41,1886.71) 4382.41,1786.71 4386.41,1786.71 ccw(c4386.41,1805.71) 4405.41,1805.71 4405.41,1805.85 cw(c4424.41,1805.85) 4443.41,1805.85 4443.41,1797.06 ccw(c4462.41,1797.06) 4481.41,1797.06 4481.41,1805.85 cw(c4500.41,1805.85) 4519.41,1805.85 4519.41,1805.71 ccw(c4538.41,1805.71) 4538.41,1786.71 4567.28,1786.71 v3(4591.46,1786.71) ; v3(5749.69,1106.49) ccw(c5749.69,1109.25) 5751.65,1107.3 R29.1@5801.34,1157
  Bottom Layer w8: v3(4591.46,1786.71) 4591.46,1647.64 ccw(c4670.56,1647.64) 4614.63,1591.7 4930.05,1276.27 4930.1,1276.23 ccw(c5339.88,1686.01) 5339.88,1106.49 5339.93,1106.49 v3(5749.69,1106.49)
TX_D0_1: J1.46 J2.25 | length 1016.9
  Bottom Layer w10: J2.25@7833.6,1334.61 7929.6,1238.61 7929.6,1026.61 8242.42,713.78 J1.46@8469.11,713.78
TX_D0_2: J22.46 R206.1 | length 650
  Top Layer w10: v1(6830.6,1052.61) v1(6830.6,1183.61)
  Bottom Layer w10: J22.46@6550.68,1185.83 6551.07,1186.22 6827.99,1186.22 v1(6830.6,1183.61) ; v1(6830.6,1052.61) 6858.24,1024.97 R206.1@7056.98,1024.97
TX_D0_LP: J19.46 R132.2 | length 296.2
  Bottom Layer w10: R132.2@7104.22,685.15 7143.64,685.15 7172.18,713.69 J19.46@7388.6,713.69
TX_D1: R27.1 U5.37 | length 2437.5
  Top Layer w8: U5.37@4051.41,1934.33 4144.09,1934.33 cw(c4144.09,1882.66) 4180.63,1919.2 4336.13,1763.7 ccw(c4371.64,1799.21) 4371.64,1748.99 4666.25,1748.99 cw(c4666.25,1648.99) 4736.96,1719.7 4762.33,1694.33 4765.16,1691.5 ccw(c4778.59,1704.94) 4792.03,1691.5 4793.73,1693.2 cw(c4807.17,1679.77) 4820.6,1693.2 cw(c4807.17,1679.77) 4820.6,1666.33 4789.57,1635.3 ccw(c4803.01,1621.87) 4789.57,1608.43 ccw(c4803.01,1621.87) 4816.44,1608.43 4847.47,1639.46 cw(c4860.91,1626.03) 4874.34,1639.46 cw(c4860.91,1626.03) 4874.34,1612.59 4843.31,1581.56 ccw(c4856.75,1568.13) 4843.31,1554.69 ccw(c4856.75,1568.13) 4870.18,1554.69 4901.21,1585.72 cw(c4914.65,1572.29) 4928.08,1585.72 cw(c4914.65,1572.29) 4928.08,1558.85 4897.05,1527.82 ccw(c4910.49,1514.39) 4897.05,1500.95 ccw(c4910.49,1514.39) 4923.92,1500.95 4954.95,1531.98 cw(c4968.39,1518.55) 4981.82,1531.98 cw(c4968.39,1518.55) 4981.82,1505.11 4980.12,1503.41 ccw(c4993.55,1489.98) 4980.12,1476.54 5004.56,1452.1 5110.76,1345.9 ccw(c5125,1360.14) v3(5125,1340) ; v3(5727.21,1341.26) ccw(c5727.21,1441.26) 5797.92,1370.55 R27.1@5801.34,1373.98
  Bottom Layer w8: v3@5125,1341.26 v3(5727.21,1341.26)
TX_D1_1: J1.44 J2.21 | length 796.8
  Top Layer w10: J2.21@7833.6,1134.61 7886.6,1134.61 v1(7968.6,1052.61)
  Bottom Layer w10: v1(7968.6,1052.61) 8275.93,745.28 J1.44@8469.11,745.28
TX_D1_2: J22.44 R205.1 | length 603.5
  Top Layer w10: v1(6896.16,1159.17) 6897.88,1157.45 6897.88,1067.32 v1(6899.6,1065.61)
  Bottom Layer w10: J22.44@6550.68,1154.33 6555.52,1159.17 6819.86,1159.17 6820.3,1158.73 6895.73,1158.73 v1(6896.16,1159.17) ; v1(6899.6,1065.61) 7023.48,1065.61 7031.39,1073.51 R205.1@7056.98,1073.51
TX_D1_LP: J19.44 R134.2 | length 289.1
  Bottom Layer w10: R134.2@7104.22,733.7 7108,733.7 7119.49,745.19 J19.44@7388.6,745.19
TX_D2: R25.1 U5.36 | length 2251.7
  Top Layer w8: U5.36@4051.41,1914.64 4138,1914.64 cw(c4138,1878.3) 4163.69,1904.01 4327.62,1740.08 ccw(c4396.56,1809.02) 4327.66,1740.04 ccw(c4396.56,1809.02) 4396.56,1711.52 4613.34,1711.52 cw(c4613.34,1611.52) 4684.05,1682.23 v3(4770,1596.28) ; v3(5733.38,1547.87) ccw(c5733.38,1622.06) 5785.85,1569.6 R25.1@5801.34,1585.09
  Bottom Layer w8: v3(4770,1596.28) 4789.13,1577.16 ccw(c4859.84,1647.87) 4859.84,1547.87 4883,1547.87 4887,1547.87 ccw(c4887,1566.87) 4906,1566.87 4906,1577.04 cw(c4925,1577.04) 4944,1577.04 4944,1526.66 ccw(c4963,1526.66) 4982,1526.66 4982,1577.04 cw(c5001,1577.04) 5020,1577.04 5020,1526.66 ccw(c5039,1526.66) 5058,1526.66 5058,1577.04 cw(c5077,1577.04) 5096,1577.04 5096,1566.87 ccw(c5115,1566.87) 5115,1547.87 5140.12,1547.87 v3(5733.38,1547.87)
TX_D2_1: J1.42 J2.17 | length 700.9
  Top Layer w10: J2.17@7833.6,934.61 v1(8130.6,934.61)
  Bottom Layer w10: v1(8130.6,934.61) 8288.43,776.77 J1.42@8469.11,776.77
TX_D2_2: J22.42 R204.1 | length 507.6
  Bottom Layer w10: J22.42@6550.68,1122.83 6550.79,1122.72 7056.32,1122.72 R204.1@7056.98,1122.06 R204.1@7056.25,1121.33
TX_D2_LP: J19.42 R135.2 | length 286.7
  Bottom Layer w10: R135.2@7104.22,782.24 7109.78,776.69 J19.42@7388.6,776.69
TX_D3: R23.1 U5.35 | length 2241
  Top Layer w8: U5.35@4051.41,1894.96 4134.57,1894.96 cw(c4134.57,1872.82) 4150.22,1888.48 4345.8,1692.9 ccw(c4416.51,1763.61) 4416.51,1663.61 v3(4635.6,1663.61) ; v3(5743.06,1758.84) ccw(c5743.06,1816.28) 5783.67,1775.66 R23.1@5801.34,1793.33
  Bottom Layer w8: v3(4635.6,1663.61) cw(c4730.83,1663.61) 4730.83,1758.84 4847.66,1758.84 4851.66,1758.84 ccw(c4851.66,1777.84) 4870.66,1777.84 4870.66,1789.84 cw(c4889.66,1789.84) 4908.66,1789.84 4908.66,1744.79 ccw(c4927.66,1744.79) 4946.66,1744.79 4946.66,1789.84 cw(c4965.66,1789.84) 4984.66,1789.84 4984.66,1744.79 ccw(c5003.66,1744.79) 5022.66,1744.79 5022.66,1789.84 cw(c5041.66,1789.84) 5060.66,1789.84 5060.66,1777.84 ccw(c5079.66,1777.84) 5079.66,1758.84 5102.67,1758.84 v3(5743.06,1758.84)
TX_D3_1: J1.40 J2.13 | length 666.3
  Top Layer w10: J2.13@7833.6,734.61 8222.6,734.61 v1(8296.6,808.61)
  Bottom Layer w10: v1(8296.6,808.61) 8468.77,808.61 J1.40@8469.11,808.27
TX_D3_2: J22.40 R203.1 | length 593.2
  Top Layer w10: v1(6954.1,1170.11) 6956.35,1167.86 6956.35,1092.86 v1(6958.6,1090.61)
  Bottom Layer w10: J22.40@6550.68,1091.34 6551.31,1091.97 6552.68,1090.61 v1(6958.6,1090.61) ; v1(6954.1,1170.11) 7056.48,1170.11 R203.1@7056.98,1170.61
TX_D3_LP: J19.40 R136.2 | length 293.7
  Bottom Layer w10: R136.2@7104.22,830.79 7143.49,830.79 7166.1,808.18 J19.40@7388.6,808.18
TXCLK_CS: J4.36 R20.2 | length 904.2
  Top Layer w8: R20.2@5848.59,942.76 ccw(c5882.35,976.52) 5882.35,928.77 5983.42,928.77 ccw(c5983.42,988.99) v3(6025.98,946.43)
  Bottom Layer w8: v3(6025.98,946.43) 6025.98,1268.78 cw(c6125.98,1268.78) 6055.27,1339.49 6199.91,1484.13 cw(c6235.19,1448.85) 6220.5,1496.53 cw(c6235.19,1448.85) 6235.19,1498.74 J4.36@6308.86,1498.74
TXD0_CS: J4.46 R29.2 | length 865.4
  Top Layer w8: R29.2@5848.59,1157 5872.42,1180.83 ccw(c5857.5,1195.75) 5878.6,1195.75 v3(5878.6,1241.61)
  Bottom Layer w8: v3(5878.6,1241.61) cw(c5878.6,1266.74) 5853.47,1266.74 5853.47,1433.04 cw(c5953.47,1433.04) 5882.76,1503.75 6005.93,1626.93 cw(c6076.64,1556.22) 6076.64,1656.22 J4.46@6308.86,1656.22
TXD1_CS: J4.44 R27.2 | length 720.2
  Top Layer w8: R27.2@5848.59,1373.98 5868.2,1354.36 cw(c5833.45,1319.61) 5876.63,1343.08 cw(c5833.45,1319.61) 5881.48,1330.04 cw(c5833.45,1319.61) v3(5882.6,1319.61)
  Bottom Layer w8: v3(5882.6,1319.61) 5932,1319.61 ccw(c5932,1419.61) 6032,1419.61 6032,1544 cw(c6112.72,1544) 6112.72,1624.72 J4.44@6308.86,1624.72
TXD2_CS: J4.42 R25.2 | length 906.6
  Top Layer w8: R25.2@5848.59,1585.09 5848.59,1572.21 ccw(c5868.2,1572.21) 5868.2,1552.6 5876.89,1552.6 cw(c5876.89,1535.24) 5894.26,1535.24 5894.26,1497.06 ccw(c5912.96,1497.06) 5912.96,1478.35 5917.8,1478.35 ccw(c5917.8,1496.14) 5935.59,1496.14 5935.59,1536.35 cw(c5956.25,1536.35) 5945.85,1554.21 cw(c5956.25,1536.35) 5956.25,1557.02 cw(c5956.25,1535.79) 5977.36,1537.99 cw(c5956.25,1535.79) 5977.48,1535.79 5977.48,1491.67 ccw(c5999.82,1491.67) 5999.82,1469.33 6004.29,1469.33 ccw(c6004.29,1487.76) 6022.72,1487.76 6022.72,1575.72 cw(c6048.82,1575.72) 6048.82,1601.82 cw(c6048.82,1571.6) 6079.04,1571.6 v3(6079.02,1520.88)
  Bottom Layer w8: v3(6079.02,1520.88) 6079.02,1544.82 cw(c6125.38,1544.82) 6092.6,1577.61 cw(c6130.31,1539.89) 6130.31,1593.23 J4.42@6308.86,1593.23
TXD3_CS: J4.40 R23.2 | length 917.1
  Top Layer w8: R23.2@5848.59,1793.33 5869.59,1772.33 cw(c5813.84,1716.58) 5881.7,1756.72 cw(c5813.84,1716.58) 5892.69,1716.58 5892.69,1694.43 ccw(c5909.58,1694.43) 5909.58,1677.54 5912.96,1677.54 ccw(c5912.96,1695.11) 5930.53,1695.11 5930.53,1746.91 cw(c5949.46,1746.91) 5949.46,1765.84 5951.88,1765.84 cw(c5951.88,1747.98) 5969.73,1747.98 5969.73,1692.63 ccw(c5985.88,1692.63) 5985.88,1676.48 5990.08,1676.48 ccw(c5990.08,1697.46) 6011.06,1697.46 6011.06,1731.56 cw(c6047.71,1731.56) 6047.71,1768.21 6068.56,1768.21 cw(c6068.56,1725.42) 6111.36,1725.42 6111.36,1710.46 ccw(c6195.34,1710.46) 6129,1658.96 cw(c6093.77,1623.72) 6134.08,1653.01 cw(c6093.77,1623.72) 6143.6,1623.72 v3(6143.6,1562.61)
  Bottom Layer w8: v3(6143.6,1562.61) ccw(c6145.71,1564.72) 6145.71,1561.73 J4.40@6308.86,1561.73
USB_N: J42.2 R181.1 | length 201.8
  Top Layer w5: R181.1@5122,5848.62 cw(c5131.51,5848.62) 5124.78,5855.34 5134.68,5865.24 ccw(c5127.42,5872.5) 5137.69,5872.5 5137.69,5891.06 ccw(c5125.38,5891.06) v4(5125.38,5903.37)
  Bottom Layer w5: v4(5125.38,5903.37) cw(c5131.3,5903.37) 5127.12,5907.55 5134.84,5915.28 ccw(c5129.06,5921.07) 5137.24,5921.01 ; J42.2@5129.24,6031.3 5129.24,6018.25 ccw(c5142.89,6018.25) 5133.24,6008.6 cw(c5123.59,5998.95) 5137.24,5998.95 5137.24,5921.01 ; 5137.24,5921.07 cw(c5129.06,5921.07) 5137.24,5921.01
USB_P: J42.3 R182.1 | length 202.8
  Top Layer w5: v4(5159.6,5902.61) ccw(c5159.6,5890.3) 5147.29,5890.3 5147.29,5872.5 ccw(c5157.73,5872.5) 5150.35,5865.12 5160.62,5854.85 cw(c5153.9,5848.13) R182.1@5163.41,5848.13
  Bottom Layer w5: J42.3@5154.83,6031.3 5154.83,6018.25 cw(c5141.19,6018.25) 5150.84,6008.6 ccw(c5160.49,5998.95) 5146.84,5998.95 5146.84,5921.07 ccw(c5159.05,5921.07) 5150.41,5912.43 5159.14,5903.71 cw(c5158.04,5902.61) v4(5159.6,5902.61)
USB_VBUS: C19.2 C110.1 C111.1 D9.1 J21.1 R3.2 U1.53 U4.65 U13.1 U13.2 | length 374.8
  Top Layer w9: U1.53@5384.89,5083.92 5385.08,5084.11 5385.08,5127.91 5467.17,5210 v4(5467.28,5210)
  Top Layer w10: U4.65@4531.24,4788.2 4579.76,4788.2 4585.08,4782.88 v1(4588.87,4782.88)
  Top Layer w20: v1(4935,5104.7) 4988,5104.7 R3.2@5019,5073.7
  Bottom Layer w20: C19.2@4538.76,4764.18 4570.17,4764.18 v1(4588.87,4782.88)
  other v1: 4774.6,5913.61 4347.6,5914.61 4435.6,5915.61 4673.6,5916.61 4725.6,5916.61 4525.6,5917.61 4236.6,5919.61 4606.6,5919.61
VDD1P0: C27.1 C28.1 C29.1 C30.1 C31.1 C32.1 C77.2 J17.2 J24.2 U5.8 U5.41 U5.51 | length 1074.6
  Top Layer w11.2: U5.51@3907.83,2255.08 v1@3907.83,2376.53
  Top Layer w11.8: v1@3456.63,2013.07 U5.8@3547.71,2013.07 ; U5.41@4051.41,2013.07 4242.64,2013.07
  Top Layer w12: 4242.64,2013.07 4260.76,1994.95 v1(4264.01,1994.95)
  Top Layer w13.7: v1(3418,2019.7) 3424.63,2013.07 3456.63,2013.07 v1(3450,2019.7) ; v1@3907.83,2376.53 v1(3916,2384.7) 3935,2403.7 v1(3946,2403.7)
  Bottom Layer w11: C32.1@3905.53,2302.41 3905.53,2374.23 ; 3905.53,2374.23 v1(3916,2384.7) 3910,2384.7 3905.53,2380.23 3905.53,2374.23
  Bottom Layer w20: v1(3418,2019.7) v1(3450,2019.7) 3450.55,2019.15 3523.43,2019.15 C28.1@3523.98,2018.61 C27.1@3523.98,1971.61 ; C29.1@4105.06,2021.76 4105.06,2067.77 C30.1@4104.22,2068.61 4108.16,2068.61 4129.45,2089.9 v1(4129.45,2181.1)
  Bottom Layer w35: J24.2@1763,3496.7 1774.96,3508.66 C77.2@1869,3508.66
VDDA1P8: J17.3 J23.2 R97.1 R99.1
VDDA1P8_AB: C38.1 C39.1 C75.2 R97.2 U5.16 | length 80.2
  Top Layer w11: v1(3489,1827.7) 3489,1844.7 3499.89,1855.59 U5.16@3547.71,1855.59
  other v1: 3489,1787.96 2710,5004.7 2761,5004.7 2710,5062.7 2761,5062.7
VDDA1P8_CD: C36.1 C37.1 C76.2 R99.2 U5.64 | length 92.9
  Top Layer w11: v1(3618,2322.87) 3621.17,2319.7 3640,2319.7 3651.92,2307.78 U5.64@3651.92,2255.08
  other v1: 3584,2303.7 2956,5096.7 3016,5096.7 3070,5096.7 2956,5159.7 3016,5159.7 3070,5159.7
VDDA2P5: C26.1 C33.1 C34.1 C35.1 C74.2 J17.4 J20.2 U5.4 U5.12 | length 642.8
  Top Layer w11.8: v1@3434.89,2091.81 U5.4@3547.71,2091.81 ; 3455.38,1934.33 U5.12@3547.71,1934.33
  Top Layer w13.7: v1@3410,1935.7 3410,1934.83 v1@3410.13,1934.7 ; v1(3440,1940.7) ccw(c3455.38,1956.08) 3455.38,1934.33
  Bottom Layer w20: v1(3402,2124.7) 3403.08,2124.7 3412.99,2134.61 3497.04,2134.61 3516.23,2115.42 3520.17,2115.42 C33.1@3521.98,2113.61 ; v1(3410,1940.7) v1(3440,1940.7) 3511.26,1940.7 C34.1@3517.26,1934.7 ; v1(3429.44,2098.26) 3462.09,2065.61 C26.1@3522.98,2065.61 ; C34.1@3524.17,1925.61 3524.57,1925.2 3524.57,1881.01 C35.1@3524.98,1880.61 ; C34.1@3526,1925.96 C34.1@3517.26,1934.7 ; C34.1@3526,1926.32 3517.62,1934.7 C34.1@3517.26,1934.7
  other v1: 2447.77,4396.7 2518.77,4396.7 2447.77,4462.7 2518.77,4462.7 2446.77,4527.7 2517.77,4527.7
VDDIO: C40.1 C41.1 C42.1 C43.1 C44.1 C45.1 C84.2 J17.5 P2.2 P2.4 P2.6 R47.2 R48.2 R51.2 R85.1 R86.1 R87.2 R88.1 R89.1 R147.1 R148.2 R151.2 R152.2 R153.2 R155.2 R156.2 R157.1 R159.2 R160.2 R163.2 R164.2 R165.2 R166.1 R167.2 R168.2 R169.2 R172.2 R173.2 U5.24 U5.40 U5.58 | length 1679.3
  Top Layer w11.8: U5.58@3770.03,2255.08 v1@3770.03,2344.73 ; 3789.72,1621.56 U5.24@3789.72,1751.38 ; U5.40@4051.41,1993.38 4192.31,1993.39
  Top Layer w12: 4192.31,1993.39 4224.09,1961.61 v1(4226.6,1961.61) ; v1@4227,1958.7 4231.51,1958.7 4254.2,1936.01 4263.71,1936.01 v1(4266,1933.71)
  Top Layer w13.7: v1@3770.03,2344.73 v1@3776,2350.7 ; 3789.72,1621.56 ccw(c3791.1,1621.56) 3790.12,1620.58 3798.6,1612.1 v1(3798.6,1609.64) v1(3798.6,1575.61)
  Top Layer w20: v1(3570.45,4282.17) 3571.21,4282.94 3575.15,4282.94 3611.45,4319.24 R47.2@3611.45,4323.17 ; R51.2@3663.64,4324.17 3663.64,4320.24 3697.74,4286.13 v1(3697.74,4285.36) ; v1@3774,2351 v1@3774,2385 ; R48.2@4230.1,4094.48 4230.35,4094.23 4230.35,4049.86 v1(4230.6,4049.61) ; v1(4272.6,4049.61) 4272.85,4049.86 4272.85,4093.73 R85.1@4273.1,4093.98 ; v1(5598.81,1421.22) R155.2@5647.18,1421.22 ; v1(5606.49,1205.05) 5645.1,1205.05 R152.2@5647.47,1207.42
  Bottom Layer w20: v1(239.5,-93.25) R168.2@239.5,-57.02 ; v1(326.49,-93.28) R166.1@326.49,-57.05 ; v1(729.5,-93.25) R159.2@729.5,-57.02 ; v1(812.5,-93.25) R157.1@812.5,-57.02 ; R89.1@1218.49,717.07 1220.35,715.2 1218.6,713.44 v1(1218.6,671.61) 1219.52,671.61 v1@1220.6,672.69 ; v1(1244.5,-103.25) R148.2@1244.5,-67.02 ; v1(1317.6,672.61) 1317.6,716.18 R88.1@1318.49,717.07 ; v1(1320.5,-103.25) R147.1@1320.5,-67.02 ; R86.1@1518.49,717.07 1517.6,716.18 1518.6,715.18 v1(1518.6,672.61) ; v1(3321.98,3864.39) R87.2@3358.21,3864.39 ; v1(5446.6,133.61) 5447.1,133.11 5489.48,133.11 R164.2@5489.98,132.61 ; v1(5451.31,268.61) R165.2@5491.31,268.61 ; v1(5451.31,418.62) R167.2@5491.31,418.62 ; v1(5451.31,561.16) R163.2@5491.31,561.16 ; v1(5451.31,698.36) R169.2@5491.31,698.36 ; v1(5451.31,989.59) R160.2@5491.31,989.59 ; v1(5451.31,1631.93) R151.2@5491.31,1631.93 ; v1(5451.31,2048.41) R156.2@5491.31,2048.41 ; v1(5451.31,2367.87) R173.2@5491.31,2367.87 ; v1(5451.31,2521) R172.2@5491.31,2521 ; v1(5455.02,1840.17) R153.2@5495.02,1840.17
  other v1: 4404.51,1980.8 4435.92,1983.89 4419.43,2008.83 3774.5,2351 3773.5,2385 3182,3792.7 3247,3792.7 3182,3857.7 3247,3857.7 3182,3922.7 3247,3922.7 3182,3987.7 3247,3987.7
VDDIOSEL_0: J36.1 U5.22 | length 2736.1
  Top Layer w8: U5.22@3750.35,1751.38 3750.35,1574.5 ccw(c3850.35,1574.5) 3779.64,1503.79 3907.31,1376.12 cw(c3836.6,1305.4) 3936.6,1305.4 3936.6,1297.61 ccw(c4006.61,1297.61) 3957.07,1248.13 ; 3957.1,1248.1 4835.42,369.79 ccw(c4906.13,440.5) 4906.13,340.5 5606.09,340.5 cw(c5606.09,240.5) 5676.8,311.21 J36.1@5718.99,269.01
VDDIOSEL_1: J35.1 U5.21 | length 2850.3
  Top Layer w8: U5.21@3730.66,1751.38 3730.66,1563.78 ccw(c3830.66,1563.78) 3731.33,1552.26 ccw(c3830.66,1563.78) 3759.95,1493.07 3839.71,1413.31 cw(c3769,1342.6) 3869,1342.6 3869,1291.63 ccw(c3969,1291.63) 3898.29,1220.92 4886.93,232.27 ccw(c4957.64,302.98) 4957.64,202.98 5606.26,202.98 cw(c5606.26,102.98) 5676.98,173.69 J35.1@5718.99,131.67
XI: R82.2 R84.2 U5.26 | length 569.2
  Top Layer w10: U5.26@3829.09,1751.38 3829.09,1649.79 3855.6,1623.28 v4(3855.6,1566.61)
  Bottom Layer w10: v4(3855.6,1566.61) 3898.03,1566.61 cw(c3898.03,1498.84) 3945.93,1546.77 3965.8,1526.9 ccw(c4036.52,1597.61) 4036.52,1497.61 R84.2@4146.1,1497.61 ; R82.2@4146.1,1444.98 R84.2@4146.1,1497.61 ; R84.2@4146.1,1506.61 R84.2@4146.1,1497.61
XO: R77.2 U5.25 | length 294.9
  Top Layer w10: U5.25@3809.4,1751.38 3809.4,1640.3 3830.64,1619.06 3830.64,1555.91 v4@3862.41,1524.14
  Bottom Layer w10: v4(3862.04,1525.4) 3864.76,1522.68 R77.2@3906.6,1522.68
XTAL1: U14.30 Y3.1 | length 103.8
  Top Layer w9: U14.30@5189.9,5583.03 5208.67,5583.03
  Top Layer w10: 5208.67,5583.03 5240.33,5583.03 v1(5247,5589.7)
  Bottom Layer w10: v1(5247,5589.7) 5259,5601.7 Y3.1@5286,5601.7
XTAL2: U14.29 Y3.3 | length 190.5
  Top Layer w10: U14.29@5189.9,5563.35 5189.98,5563.27 5212.84,5563.27 5253.6,5522.51 v1(5253.6,5488.61)
  Bottom Layer w10: v1(5253.6,5488.61) 5253.75,5488.45 5329.3,5488.45 Y3.3@5329.46,5488.29
pads on no net: FID1.1 FID2.1 FID3.1 FID4.1 FID5.1 FID6.1 FID7.1 FID8.1 FID9.1 FID10.1 FID11.1 FID12.1 FID13.1 FID14.1 FID15.1 FID16.1 FID17.1 FID18.1 H1.0 H2.0 H3.0 H4.0 H5.0 H6.0 H7.0 H8.0 J1.2 J1.4 J1.11 J1.14 J1.17 J1.27 J1.33 J1.53 J1.55 J1.57 J1.59 J4.2 J4.4 J4.11 J4.14 J4.17 J4.27 J4.33 J4.53 J4.55 J4.57 J4.59 J19.2 J19.4 J19.11 J19.14 J19.17 J19.27 J19.33 J19.53 J19.55 J19.57 J19.59 J22.2 J22.4 J22.11 J22.14 J22.17 J22.27 J22.33 J22.53 J22.55 J22.57 J22.59 J42.4 U1.3 U1.4 U1.5 U1.6 U1.7 U1.8 U1.10 U1.12 U1.13 U1.18 U1.19 U1.22 U1.23 U1.24 U1.25 U1.26 U1.27 U1.28 U1.29 U1.30 U1.31 U1.34 U1.35 U1.36 U1.41 U1.42 U1.45 U1.46 U1.47 U1.48 U1.60 U1.61 U1.62 U1.63 U4.5 U4.6 U4.7 U4.8 U4.9 U4.10 U4.12 U4.13 U4.15 U4.16 U4.17 U4.25 U4.26 U4.27 U4.35 U4.36 U4.39 U4.40 U4.41 U4.42 U4.43 U4.44 U4.47 U4.48 U4.53 U4.54 U4.55 U4.56 U4.57 U4.58 U4.59 U4.60 U4.72 U4.73 U4.74 U4.75 U5.1 U5.7 U5.9 U5.17 U5.18 U5.19 U5.20 U6.8 U11.3@1624.13,1936.31 U11.8@1657,1936.31 U12.3@1624.13,2182.31 U12.8@1657,2182.31 U14. U14.5 U14.9 U14.13 U14.17 U14.21 U14.32

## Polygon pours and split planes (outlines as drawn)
GND on Top Layer "GND_L01_P726" (solid, remove dead copper, pour order 726): 22 vertices, not listed, extent -160,-150.65 6359,6157.78
GND_2 on Top Layer "GND_2" (solid, remove dead copper, pour order 709): 27 vertices, not listed, extent 6502,-169 7453,2087
RJ45_ERTH on Top Layer "Bottom Layer-No Net" (solid, remove dead copper, pour order 723): -160,1186.2 -115.4,1141.61 111.6,1141.61 187.6,1217.61 187.6,1490.61 213.6,1517.35 480.62,1517.35 529,1565.73 529,1621.64 529,2418.64 485.36,2462.28 -110.72,2462.28 -160,2413
GND_1 on Top Layer "GND_2" (solid, remove dead copper, pour order 710): 17 vertices, not listed, extent 7582,-160 8512,2066
5V on Top Layer "5V_L01_P699" (solid, remove dead copper, pour order 699): 928.6,5710.61 900.6,5738.61 900.6,5886.61 912.6,5898.61 1296.6,5898.61 1314.6,5880.61 1314.6,5681.61 1276.6,5643.61 1191.6,5643.61 1122.6,5574.61 946.6,5574.61 928.6,5592.61
VDDA1P8_AB on Top Layer "VDDA1P8_AB_L01_P651" (solid, remove dead copper, pour order 651): 3492.23,1861.63 3475.52,1844.92 3475.52,1781.05 3489,1767.57 3582.45,1767.57 3608.52,1793.64 3608.52,1854.47 3599.31,1863.68 3495.18,1863.68 3493.87,1862.37
GND on Top Layer "GND_L01_P706" (solid, remove dead copper, pour order 706): 17 vertices, not listed, extent 3449.65,4371.32 3561.6,4467.61
GND on Top Layer "Bottom Layer-No Net" (solid, remove dead copper, pour order 678): 3668.51,4936.7 3608,4936.7 3602,4942.7 3602,5329.7 3608,5335.7 3697,5335.7 3705,5327.7 3705,4942.7 3699,4936.7
MCU_VCC on Top Layer "Bottom Layer-No Net" (solid, remove dead copper, pour order 675): 4006.6,5729.61 4001.6,5734.61 4001.6,5791.61 4011.99,5802 4118.6,5802 4148.99,5771.61 4224.6,5771.61 4320.6,5771.61 4322.6,5769.61 4322.6,5728.61 4321.6,5727.61 4152.6,5727.61 4150.6,5729.61
NetC13_1 on Top Layer "NETC13_1_L01_P707" (solid, remove dead copper, pour order 707): 3522.39,4473.98 3487,4473.98 3433.6,4473.98 3429.9,4477.68 3429.9,4521.91 3435.6,4527.61 3550.98,4527.61 3575.6,4502.98 3575.6,4480.98 3573.6,4478.98 3527.39,4478.98
no net on Top Layer "NONET_L01_P705" (solid, pour order 705): 4726.6,5216.61
MCU_VCC on Top Layer "MCU_VCC_L01_P704" (solid, remove dead copper, pour order 704): 4726.6,5216.61 4807.6,5216.61 4823.6,5200.61 4823.6,5028.61 4809.6,5014.61 4727.13,5014.61 4721.6,5020.14 4721.6,5210.13
no net on Top Layer "NONET_L01_P703" (solid, pour order 703): 4735.38,5186.61
GND on Top Layer "GND_L01_P702" (solid, remove dead copper, pour order 702): 19 vertices, not listed, extent 4059.6,4131.61 4159.6,4242.61
NetC14_1 on Top Layer "NETC14_1_L01_P701" (solid, remove dead copper, pour order 701): 4126.41,4242.61 4083,4242.61 4078,4237.61 4034.6,4237.61 4027.6,4244.61 4027.6,4284.61 4030.6,4287.61 4155.6,4287.61 4171.6,4271.61 4171.6,4249.61 4169.6,4247.61 4131.41,4247.61
USB_VBUS on Top Layer "USB_VBUS_L01_P700" (solid, remove dead copper, pour order 700): 19 vertices, not listed, extent 3913.6,5782.2 4885.6,6134.7
1V8 on Top Layer "Bottom Layer-No Net" (solid, pour order 655): 19 vertices, not listed, extent 701,5091.7 1703,5347.7
5V on Top Layer "Bottom Layer-No Net" (solid, remove dead copper, pour order 673): 28 vertices, not listed, extent 223.6,3274.61 594,3447.7
NetC56_2 on Top Layer "NETC56_2_L01_P682" (solid, remove dead copper, pour order 682): 18 vertices, not listed, extent 608.98,5727.61 825.6,5840.57
no net on Top Layer "NONET_L01_P683" (solid, pour order 683): 640.22,5828.09
5V-36V on Top Layer "5V-36V_L01_P638" (solid, remove dead copper, pour order 638): 20 vertices, not listed, extent 595.6,5528.61 788.6,5786.61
